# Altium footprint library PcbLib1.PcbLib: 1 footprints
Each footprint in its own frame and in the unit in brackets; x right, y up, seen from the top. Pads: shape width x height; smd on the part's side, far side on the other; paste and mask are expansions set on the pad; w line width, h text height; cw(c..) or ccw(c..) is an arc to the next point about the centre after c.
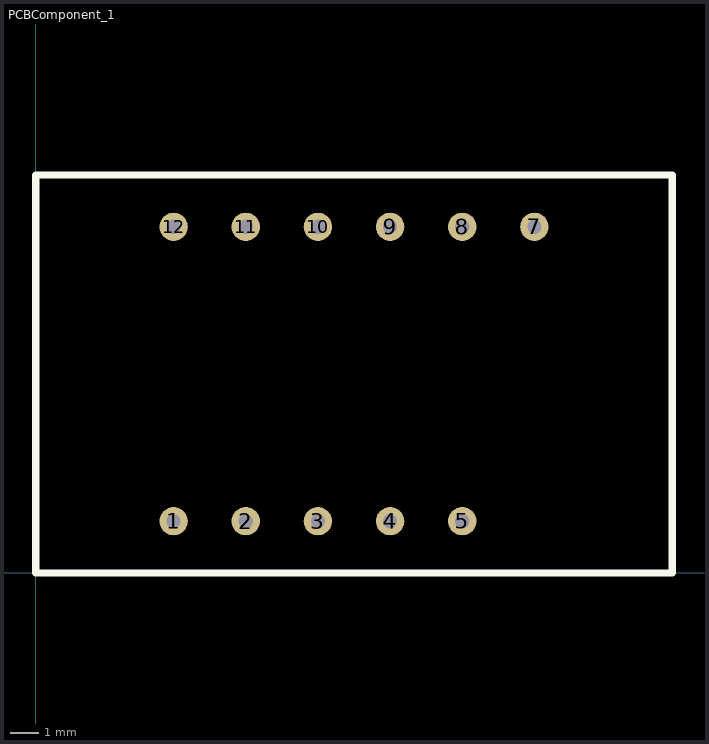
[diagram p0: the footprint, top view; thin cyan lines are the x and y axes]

## PCBComponent_1 [mm]
pads (11):
  round 1 hole 0.5: 1(4.85,1.82) 2(7.39,1.82) 3(9.93,1.82) 4(12.47,1.82) 5(15.01,1.82) 7(17.55,12.18) 8(15.01,12.18) 9(12.47,12.18) 10(9.93,12.18) 11(7.39,12.18) 12(4.85,12.18)
Top Overlay:
  lines w0.254: 0,0 22.4,0 22.4,14 0,14 0,0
